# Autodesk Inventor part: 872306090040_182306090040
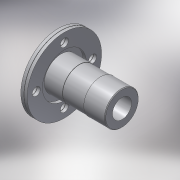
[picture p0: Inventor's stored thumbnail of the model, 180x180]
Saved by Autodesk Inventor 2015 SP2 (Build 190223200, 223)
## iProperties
Created: 2017-02
Part Number: 872306090040_182306090040
Material: PVC-Piping
Description: PLASSON FLANGE ADAPTOR WITH METAL FLANGE 90-4"
Document SubType Name: Modeling
Designer: KIM
Mass: 92.6774 g
Surface Area: 199.44 cm^2
Volume: 66.1981 cm^3
Density: 1.4 g/cm^3
Appearance: Smooth - White
Author: Кирилл
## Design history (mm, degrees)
derived "872306.ipt"
feature "Solid1::872306.ipt"
tag "TaggingFeature1"
body "Solid1"
other parameters: "d73" = 17.5, "d74" = 90 deg, "d75" = 0.3, "d77" = 18, "d80" = 0, "d82" = 360 deg, "d96" = 0.3, "d99" = 360 deg, "d103" = 175, "d104" = 1.8, "d107" = 117, "d108" = 4.375, "d116" = 88.2, "d117" = 58.33333, "d118" = 58.33333, "d120" = 10.8, "H_" = 175, "S_" = 18
